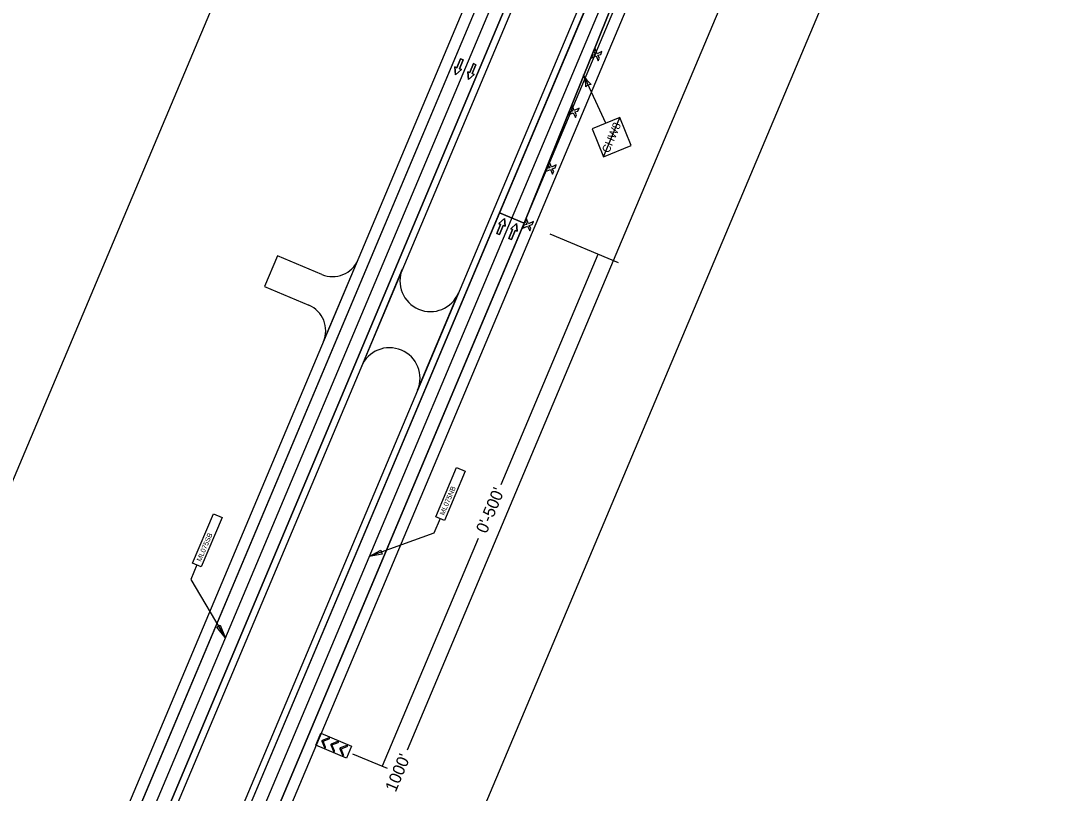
# Model space of a CAD drawing. Extents: x 14104283 to 14129344, y 8637090 to 8673339.
# Drawn here: x 14117797 to 14118725, y 8666247 to 8666942 of the extents above; entities that cross this region are included whole.
import ezdxf

# ---------------------------------------------------------------- set-up
doc = ezdxf.new("R2010")
doc.units = 0
for name, color, linetype in [('Cell', 7, 'Continuous'), ('Default', 7, 'Continuous'), ('dsnNonPlotable', 7, 'Continuous'), ('dsnPaintExistingBrokenLaneLineWhite', 7, 'Continuous'), ('dsnPaintExistingEdgeLineLeftYellow', 7, 'Continuous'), ('dsnPaintExistingEdgeLineRightWhite', 7, 'Continuous'), ('dsnShadingPaved', 7, 'Continuous'), ('dsnStdLabel', 7, 'Continuous'), ('dsnStgShadingPrevPav', 7, 'Continuous'), ('dsnTapePlaceChannelizingLaneWhite', 7, 'Continuous'), ('Text', 7, 'Continuous')]:
    doc.layers.add(name, color=color, linetype=linetype)

msp = doc.modelspace()

# ---------------------------------------------------------------- linework, layer by layer
at = {"layer": 'Cell'}
for p, q in [((14118311.31, 8666911.15), (14118310.28, 8666908.6)), ((14118310.28, 8666908.6), (14118314.67, 8666910.47)), ((14118314.05, 8666911.93), (14118311.31, 8666911.15)), ((14118313.65, 8666916.95), (14118312.62, 8666914.4)), ((14118312.62, 8666914.4), (14118314.05, 8666911.93)), ((14118315.52, 8666912.56), (14118313.65, 8666916.95)), ((14118314.67, 8666910.47), (14118316.54, 8666906.08)), ((14118319.91, 8666914.43), (14118315.52, 8666912.56)), ((14118316.14, 8666911.09), (14118318.88, 8666911.88)), ((14118317.57, 8666908.63), (14118316.14, 8666911.09)), ((14118318.88, 8666911.88), (14118319.91, 8666914.43)), ((14118316.54, 8666906.08), (14118317.57, 8666908.63)), ((14118293.09, 8666865.93), (14118292.07, 8666863.38)), ((14118294.96, 8666861.54), (14118293.09, 8666865.93)), ((14118290.76, 8666860.14), (14118289.73, 8666857.59)), ((14118289.73, 8666857.59), (14118294.12, 8666859.46)), ((14118293.5, 8666860.92), (14118290.76, 8666860.14)), ((14118292.07, 8666863.38), (14118293.5, 8666860.92)), ((14118294.12, 8666859.46), (14118295.99, 8666855.06)), ((14118299.35, 8666863.41), (14118294.96, 8666861.54)), ((14118295.59, 8666860.08), (14118298.33, 8666860.86)), ((14118297.02, 8666857.61), (14118295.59, 8666860.08)), ((14118295.99, 8666855.06), (14118297.02, 8666857.61)), ((14118298.33, 8666860.86), (14118299.35, 8666863.41)), ((14118270.2, 8666809.12), (14118269.18, 8666806.57)), ((14118269.18, 8666806.57), (14118273.57, 8666808.44)), ((14118272.94, 8666809.9), (14118270.2, 8666809.12)), ((14118272.54, 8666814.92), (14118271.51, 8666812.37)), ((14118271.51, 8666812.37), (14118272.94, 8666809.9)), ((14118274.41, 8666810.53), (14118272.54, 8666814.92)), ((14118273.57, 8666808.44), (14118275.44, 8666804.05)), ((14118278.8, 8666812.4), (14118274.41, 8666810.53)), ((14118275.03, 8666809.06), (14118277.77, 8666809.85)), ((14118276.46, 8666806.6), (14118275.03, 8666809.06)), ((14118277.77, 8666809.85), (14118278.8, 8666812.4)), ((14118275.44, 8666804.05), (14118276.46, 8666806.6)), ((14118251.99, 8666763.9), (14118250.96, 8666761.35)), ((14118253.86, 8666759.51), (14118251.99, 8666763.9)), ((14118249.65, 8666758.11), (14118248.62, 8666755.56)), ((14118248.62, 8666755.56), (14118253.01, 8666757.43)), ((14118252.39, 8666758.89), (14118249.65, 8666758.11)), ((14118250.96, 8666761.35), (14118252.39, 8666758.89)), ((14118253.01, 8666757.43), (14118254.88, 8666753.03)), ((14118258.25, 8666761.38), (14118253.86, 8666759.51)), ((14118254.48, 8666758.05), (14118257.22, 8666758.83)), ((14118255.91, 8666755.58), (14118254.48, 8666758.05)), ((14118254.88, 8666753.03), (14118255.91, 8666755.58)), ((14118257.22, 8666758.83), (14118258.25, 8666761.38)), ((14118067.91, 8666293.84), (14118070.26, 8666288.07)), ((14118075.99, 8666290.44), (14118078.34, 8666284.67)), ((14118084.12, 8666287.01), (14118086.47, 8666281.24))]:
    msp.add_line(p, q, dxfattribs=at)
for points in [[(14118192.67, 8666908.01), (14118194.98, 8666907.06), (14118191.66, 8666898.97), (14118193.4, 8666898.26), (14118188.13, 8666893.66), (14118187.61, 8666900.63), (14118189.35, 8666899.92)], [(14118204.17, 8666903.61), (14118206.49, 8666902.66), (14118203.16, 8666894.57), (14118204.9, 8666893.86), (14118199.64, 8666889.26), (14118199.12, 8666896.23), (14118200.85, 8666895.52)], [(14118227.71, 8666749.82), (14118225.4, 8666750.77), (14118228.72, 8666758.87), (14118226.99, 8666759.58), (14118232.25, 8666764.17), (14118232.77, 8666757.21), (14118231.03, 8666757.92)], [(14118238.48, 8666745.29), (14118236.17, 8666746.23), (14118239.49, 8666754.33), (14118237.76, 8666755.04), (14118243.02, 8666759.64), (14118243.54, 8666752.67), (14118241.8, 8666753.38)], [(14118090.14, 8666278.65), (14118062.5, 8666290.3), (14118066.95, 8666300.87), (14118094.6, 8666289.22)]]:
    msp.add_lwpolyline(points, close=True, dxfattribs=at)
for points in [[(14118189.35, 8666899.92), (14118187.61, 8666900.63), (14118188.13, 8666893.66), (14118193.4, 8666898.26), (14118191.66, 8666898.97), (14118194.98, 8666907.06), (14118192.67, 8666908.01), (14118189.35, 8666899.92)], [(14118200.85, 8666895.52), (14118199.12, 8666896.23), (14118199.64, 8666889.26), (14118204.9, 8666893.86), (14118203.16, 8666894.57), (14118206.49, 8666902.66), (14118204.17, 8666903.61), (14118200.85, 8666895.52)], [(14118231.03, 8666757.92), (14118232.77, 8666757.21), (14118232.25, 8666764.17), (14118226.99, 8666759.58), (14118228.72, 8666758.87), (14118225.4, 8666750.77), (14118227.71, 8666749.82), (14118231.03, 8666757.92)], [(14118241.8, 8666753.38), (14118243.54, 8666752.67), (14118243.02, 8666759.64), (14118237.76, 8666755.04), (14118239.49, 8666754.33), (14118236.17, 8666746.23), (14118238.48, 8666745.29), (14118241.8, 8666753.38)], [(14118073.98, 8666296.88), (14118073.96, 8666296.87), (14118068.19, 8666294.52), (14118068.18, 8666294.52)], [(14118071.21, 8666288.46), (14118071.2, 8666288.48), (14118068.86, 8666293.84), (14118074.33, 8666295.91)], [(14118082.06, 8666293.47), (14118082.04, 8666293.46), (14118076.27, 8666291.12), (14118076.27, 8666291.11)], [(14118079.29, 8666285.05), (14118079.28, 8666285.08), (14118076.94, 8666290.44), (14118082.42, 8666292.51)], [(14118090.19, 8666290.05), (14118090.17, 8666290.04), (14118084.4, 8666287.69), (14118084.4, 8666287.69)], [(14118087.42, 8666281.63), (14118087.41, 8666281.65), (14118085.07, 8666287.01), (14118090.55, 8666289.08)]]:
    msp.add_lwpolyline(points, dxfattribs=at)
for centre, start, end in [((14118068.38, 8666294.04), 112.54487, 202.99314), ((14118070.73, 8666288.27), 201.87368, 22.05724), ((14118074.16, 8666296.4), 289.79452, 110.9537), ((14118076.46, 8666290.64), 112.54487, 202.99314), ((14118082.24, 8666292.99), 289.79452, 110.9537), ((14118090.37, 8666289.57), 289.79452, 110.9537), ((14118078.82, 8666284.86), 201.87368, 22.05724), ((14118084.6, 8666287.21), 112.54487, 202.99314), ((14118086.95, 8666281.43), 201.87368, 22.05724)]:
    msp.add_arc(centre, 0.515, start, end, dxfattribs=at)
at = {"layer": 'Default'}
for points in [[(14118413.25, 8667444.25), (14110818.39, 8649409.15), (14109142.61, 8645431.44)], [(14109164.73, 8645422.12), (14110840.51, 8649399.84), (14118435.37, 8667434.94)]]:
    msp.add_lwpolyline(points, dxfattribs=at)
at = {"layer": 'dsnNonPlotable'}
msp.add_lwpolyline([(14117486.73, 8665809.52), (14118095.31, 8667254.06), (14118560.69, 8667058), (14117952.12, 8665613.46)], close=True, dxfattribs=at)
at = {"layer": 'dsnPaintExistingBrokenLaneLineWhite'}
for p, q in [((14114932.53, 8658913.38), (14118863.73, 8668248.6)), ((14110829.45, 8649404.5), (14118424.31, 8667439.59))]:
    msp.add_line(p, q, dxfattribs=at)
at = {"layer": 'dsnPaintExistingEdgeLineLeftYellow'}
for p, q in [((14115900.95, 8661243.95), (14118759.37, 8668031.7)), ((14118435.37, 8667434.94), (14115816.14, 8661215.2)), ((14118435.37, 8667434.94), (14115816.14, 8661215.2))]:
    msp.add_line(p, q, dxfattribs=at)
at = {"layer": 'dsnPaintExistingEdgeLineRightWhite'}
for p, q in [((14110924.38, 8649364.51), (14118874.68, 8668243.67)), ((14118413.25, 8667444.25), (14115798.75, 8661235.75))]:
    msp.add_line(p, q, dxfattribs=at)
at = {"layer": 'dsnShadingPaved'}
for p, q in [((14118227.72, 8666769.23), (14118759.37, 8668031.7)), ((14118537.63, 8667474.22), (14118249.84, 8666759.92)), ((14115901.18, 8661244.5), (14118227.72, 8666769.23)), ((14118249.84, 8666759.92), (14118227.72, 8666769.23)), ((14118227.72, 8666769.23), (14118249.84, 8666759.92)), ((14118249.84, 8666759.92), (14115923.29, 8661235.18))]:
    msp.add_line(p, q, dxfattribs=at)
at = {"layer": 'dsnStdLabel'}
for p, q in [((14118461.19, 8667037.24), (14118330.11, 8666726.11)), ((14118323.46, 8666849.94), (14118303.27, 8666893.62)), ((14118321.14, 8666819.84), (14118335.96, 8666855.03)), ((14118334.65, 8666724.2), (14118273.35, 8666750.02)), ((14118330.11, 8666726.11), (14118144.58, 8666285.72)), ((14118316.29, 8666731.94), (14118228.93, 8666524.57)), ((14118208.55, 8666476.19), (14118122.17, 8666271.16)), ((14118126.78, 8666269.22), (14118095.84, 8666282.24))]:
    msp.add_line(p, q, dxfattribs=at)
msp.add_lwpolyline([(14118321.14, 8666819.84), (14118346.14, 8666830.02), (14118335.96, 8666855.03), (14118310.96, 8666844.84)], close=True, dxfattribs=at)
for centre, radius, start, end in [((14118282.43, 8666884), 22.95, 356.73394, 24.80525), ((14118324.1, 8666903.25), 22.95, 204.8051, 232.87636), ((14118311.34, 8666876.16), 8.86, 97.07093, 132.53937)]:
    msp.add_arc(centre, radius, start, end, dxfattribs=at)
at = {"layer": 'dsnStgShadingPrevPav'}
for p, q in [((14115895.65, 8661246.83), (14118811.53, 8668171.01)), ((14118848.39, 8668155.49), (14115932.51, 8661231.3)), ((14118653.02, 8668013.62), (14115794.02, 8661224.52)), ((14115816.14, 8661215.2), (14118675.14, 8668004.3)), ((14115816.14, 8661215.2), (14118675.14, 8668004.3)), ((14118680.66, 8668001.98), (14115821.67, 8661212.88)), ((14110809.18, 8649413.03), (14118404.03, 8667448.13)), ((14118413.25, 8667444.25), (14110818.39, 8649409.15)), ((14118027.88, 8666730.65), (14118016.23, 8666703)), ((14118067.7, 8666713.88), (14118027.88, 8666730.65)), ((14118069.39, 8666653.49), (14118100.44, 8666727.21)), ((14118140.22, 8666718.6), (14118103.35, 8666631.05)), ((14118016.23, 8666703), (14118056.06, 8666686.23)), ((14118154.04, 8666609.7), (14118190.91, 8666697.26))]:
    msp.add_line(p, q, dxfattribs=at)
for centre, radius, start, end in [((14118077.4, 8666736.92), 25, 247.1633, 337.1633), ((14118165.56, 8666707.93), 27.5, 157.1633, 247.1633), ((14118165.56, 8666707.93), 27.5, 247.1633, 337.1633), ((14118046.35, 8666663.19), 25, 337.1633, 67.1633), ((14118128.69, 8666620.38), 27.5, 67.1633, 157.1633), ((14118128.69, 8666620.38), 27.5, 337.1633, 67.1633)]:
    msp.add_arc(centre, radius, start, end, dxfattribs=at)
at = {"layer": 'dsnTapePlaceChannelizingLaneWhite'}
msp.add_line((14118249.84, 8666759.92), (14118537.63, 8667474.22), dxfattribs=at)
at = {"layer": 'Text'}
for points in [[(14118170.31, 8666495.71), (14118188.98, 8666540.05), (14118196.72, 8666536.78), (14118178.05, 8666492.45)], [(14118170.31, 8666495.71), (14118188.98, 8666540.05), (14118196.72, 8666536.78), (14118178.05, 8666492.45)], [(14117951.55, 8666454.11), (14117970.23, 8666498.44), (14117977.97, 8666495.18), (14117959.29, 8666450.84)], [(14117951.55, 8666454.11), (14117970.23, 8666498.44), (14117977.97, 8666495.18), (14117959.29, 8666450.84)], [(14118110.47, 8666459.86), (14118120.97, 8666465.56), (14118122.17, 8666462.23)], [(14117980.73, 8666387.02), (14117973.19, 8666396.29), (14117976.24, 8666398.09)]]:
    msp.add_lwpolyline(points, close=True, dxfattribs=at)
for points in [[(14118174.18, 8666494.08), (14118168.54, 8666480.93), (14118110.47, 8666459.86)], [(14117955.42, 8666452.47), (14117949.79, 8666439.33), (14117980.73, 8666387.02)]]:
    msp.add_lwpolyline(points, dxfattribs=at)

# ---------------------------------------------------------------- texts
at = {"layer": 'dsnStdLabel'}
for s, height, p in [('CHW8', 7.2, (14118326.2, 8666822.59)), ("0'-500'", 10.8, (14118216.02, 8666480.03)), ("1000'", 10.8, (14118134.28, 8666247.35))]:
    msp.add_text(s, height=height, rotation=67.1547, dxfattribs=at).set_placement(p)
at = {"layer": 'Text'}
for s, p in [('ML075NB', (14118177.77, 8666496.68)), ('ML075SB', (14117959.02, 8666455.07))]:
    msp.add_text(s, height=4.484, rotation=67.1547, dxfattribs=at).set_placement(p)

doc.saveas('drawing.dxf')
